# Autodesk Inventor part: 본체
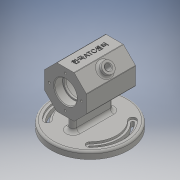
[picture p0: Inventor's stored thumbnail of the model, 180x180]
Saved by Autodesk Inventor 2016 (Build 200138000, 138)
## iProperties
Created: 2017-06
Part Number: 본체
Material: 일반
Document SubType Name: Modeling
Designer: USER
Density: 1 g/cm^3
Appearance: 기본값
Author: USER
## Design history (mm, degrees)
sketch "스케치1"
  geometry: L1 (0, 0)-(0, 30); L2 (0, 0)-(-12.426, 30); L3 (0, 0)-(12.426, 30); L4 (0, 0)-(12.426, -30); L5 (0, 0)-(-12.426, -30); L6 (0, 0)-(30, 12.426); L7 (0, 0)-(30, -12.426); L8 (0, 0)-(-30, 12.426); L9 (0, 0)-(-30, -12.426); L10 (0, 0)-(30, 0); L11 (0, 0)-(-30, 0); L12 (0, 0)-(0, -30); L13 (30, 12.426)-(30, -12.426); L14 (-12.426, -30)-(12.426, -30); L15 (-30, 12.426)-(-30, -12.426); L16 (-12.426, 30)-(12.426, 30); L17 (-12.426, 30)-(-30, 12.426); L18 (12.426, 30)-(30, 12.426); L19 (30, -12.426)-(12.426, -30); L20 (-12.426, -30)-(-30, -12.426); A1 r 30 centre (0, 0) between (0, 30) and (-30, 0); 7 further points
  constraints: 40 end point, 4 horizontal, 4 point on circle, 4 point on line, 4 vertical, 3 horizontal alignment, 2 vertical alignment, 1 centre point, 1 coincident, 1 perpendicular
  dimensions: "d0" = 60 diameter of A1; "d1" = 22.5 deg angle of L1 L2; "d2" = 22.5 deg angle of L1 L3; "d4" = 22.5 deg angle of L11 L8; "d5" = 22.5 deg angle of L11 L9; "d6" = 22.5 deg angle of L12 L5; "d7" = 22.5 deg angle of L4 L12; "d8" = 22.5 deg angle of L10 L7
extrude "돌출1" new body sketch "스케치1" distance "d9" = 70; taper "d10" = 0 deg
sketch "스케치2"
  geometry: L1 (0, 0)-(0, 70); L2 (-12.426, 0)-(-30, 0) reference; L3 (-16, 0)-(-16, 12); L4 (-16, 12)-(-14, 12); L5 (-14, 12)-(-14, 15); L6 (-14, 15)-(-25, 15); L7 (-25, 15)-(-25, 55); L8 (-25, 55)-(-14, 55); L9 (-14, 55)-(-14, 58); L10 (-14, 58)-(-16, 58); L11 (-16, 58)-(-16, 70); L12 (-12.426, 70)-(-30, 70) reference; L13 (-16, 70)-(0, 70); L14 (-16, 0)-(0, 0)
  constraints: 24 end point, 7 perpendicular, 3 point on line, 3 vertical, 1 horizontal, 1 parallel
  dimensions: "d11" = 32 diameter of L3 L1; "d12" = 32 diameter of L11 L1; "d13" = 28 diameter of L5 L1; "d14" = 50 diameter of L7 L1; "d15" = 12 distance of L3.start L3.end; "d16" = 12 distance of L10.end L11.end; "d17" = 40 distance of L6.end L7.end; "d18" = 3 distance of L8.end L9.end
revolve "회전1" sketch "스케치2" stored, may be unused: angle "d19" = 90 deg
sketch "스케치3" dims "d20" = 46
  geometry: 3 further points
  constraints: 2 coincident, 2 horizontal alignment, 2 other
hole "구멍1" sketch "스케치3" at (-23, 0) diameter "d21" = 3.242; stored, may be unused: countersink angle "d25" = 90 deg, drill point angle "d27" = 118 deg; dims "d22" = 8, "d23" = 4, "d24" = 2, "d26" = 10
node "작업 평면1"
chamfer "모따기1" distance "d31" = 1; stored, may be unused: second distance "d32" = 2, angle "d33" = 45 deg
fillet "모깎기1" dims "d34" = 3
fillet "모깎기2" dims "d35" = 0.3
node "작업 평면2"
sketch "스케치4"
  geometry: L1 (0, 30)-(70, 30) reference; C1 r 55 at (35, 0); 2 further points
  constraints: 1 centre point, 1 horizontal alignment, 1 midpoint, 1 vertical alignment
  dimensions: "d37" = 110 diameter of C1
extrude "돌출2" join sketch "스케치4" distance "d38" = 10; taper "d39" = 0 deg
sketch "스케치5"
  geometry: L1 (0, -24)-(0, 24); L2 (5, -24)-(5, 24); L3 (-5, 24)-(-5, -24); C1 r 55 at (0, 0) reference; A1 r 5 centre (0, -24) between (-5, -24) and (5, -24); A2 r 5 centre (0, 24) between (5, 24) and (-5, 24); 2 further points
  constraints: 8 end point, 4 point on circle, 4 tangent, 2 centre point, 1 coincident, 1 midpoint, 1 parallel, 1 vertical, 1 vertical alignment
  dimensions: "d40" = 5 radius of A1; "d41" = 48 distance of L1.end L1.start
extrude "돌출3" join sketch "스케치5" stored distance "d42" = 10; taper "d43" = 0 deg
fillet "모깎기3" dims "d44" = 5
sketch "스케치6"
  geometry: L1 (0, 0)-(30.406, 30.406); L2 (0, 0)-(72.385, 0); L3 (0, 0)-(-55, 0); L4 (0, 0)-(30.406, -30.406); L5 (0, 0)-(-30.406, -30.406); L6 (0, 0)-(-30.406, 30.406); A1 r 5 centre (30.406, -30.406) between (26.87, -26.87) and (33.941, -33.941); A2 r 5 centre (30.406, 30.406) between (33.941, 33.941) and (26.87, 26.87); A3 r 5 centre (-30.406, 30.406) between (-26.87, 26.87) and (-33.941, 33.941); A4 r 5 centre (-30.406, -30.406) between (-33.941, -33.941) and (-26.87, -26.87); A5 r 38 centre (0, 0) between (-26.87, 26.87) and (-26.87, -26.87); A6 r 38 centre (0, 0) between (26.87, -26.87) and (26.87, 26.87); A7 r 48 centre (0, 0) between (-33.941, 33.941) and (-33.941, -33.941); A8 r 48 centre (0, 0) between (33.941, -33.941) and (33.941, 33.941); 1 further point
  constraints: 16 point on circle, 12 end point, 8 centre point, 5 point on line, 3 coincident, 2 horizontal, 1 horizontal alignment, 1 other
  dimensions: "d49" = 45 deg angle of L2 L1; "d51" = 10 diameter of A1; "d52" = 10 diameter of A2; "d57" = 10 diameter of A3; "d58" = 10 diameter of A4; "d59" = 45 deg angle of L2 L4; "d60" = 45 deg angle of L3 L5; "d61" = 45 deg angle of L6 L3; "d62" = 38 radius of A6; "d63" = 48 radius of A8; "d64" = 38 radius of A5; "d65" = 48 radius of A7
extrude "돌출4" cut sketch "스케치6" distance "d66" = 3; taper "d67" = 0 deg
sketch "스케치7"
  geometry: L1 (0, 0)-(69.77, 0); L2 (0, 0)-(30.406, 30.406); L3 (0, 0)-(-74.571, 0); L4 (0, 0)-(30.406, -30.406); L5 (0, 0)-(-30.406, -30.406); L6 (0, 0)-(-30.406, 30.406); C1 r 55 at (0, 0) reference; A1 r 2 centre (30.406, 30.406) between (31.82, 31.82) and (28.991, 28.991); A2 r 2 centre (30.406, -30.406) between (28.991, -28.991) and (31.82, -31.82); A3 r 2 centre (-30.406, -30.406) between (-31.82, -31.82) and (-28.991, -28.991); A4 r 2 centre (-30.406, 30.406) between (-28.991, 28.991) and (-31.82, 31.82); A5 r 41 centre (0, 0) between (-28.991, 28.991) and (-28.991, -28.991); A6 r 41 centre (0, 0) between (28.991, -28.991) and (28.991, 28.991); A7 r 45 centre (0, 0) between (-31.82, 31.82) and (-31.82, -31.82); A8 r 45 centre (0, 0) between (31.82, -31.82) and (31.82, 31.82); 1 further point
  constraints: 16 point on circle, 12 end point, 8 centre point, 7 coincident, 2 horizontal, 1 horizontal alignment, 1 vertical alignment
  dimensions: "d70" = 45 deg angle of L1 L2; "d73" = 45 deg angle of L1 L4; "d74" = 45 deg angle of L3 L5; "d75" = 45 deg angle of L6 L3; "d76" = 4 diameter of A1; "d77" = 4 diameter of A2; "d78" = 4 diameter of A3; "d79" = 4 diameter of A4; "d82" = 41 radius of A6; "d83" = 45 radius of A8; "d84" = 41 radius of A5; "d85" = 45 radius of A7; "d86" = 30.40559 distance from line of L1 L2.end
extrude "돌출5" cut sketch "스케치7" distance "d87" = 20; taper "d88" = 0 deg
node "작업 평면3"
sketch "스케치8"
  geometry: L1 (0, 0)-(-26.163, -26.163); L2 (0, 0)-(-40.912, 0)
  constraints: 4 end point, 1 horizontal
  dimensions: "d89" = 45 deg angle of L2 L1; "d90" = 37 distance of L1.start L1.end
node "작업 평면4"
sketch "스케치9"
  geometry: L1 (-35, 12.426)-(-35, -12.426) reference; L2 (-35, -12.426)-(35, -12.426) reference; L3 (35, 12.426)-(35, -12.426) reference; L4 (-35, 12.426)-(35, 12.426) reference; C1 r 8 at (0, 0); 4 further points
  constraints: 2 midpoint, 1 centre point, 1 coincident, 1 horizontal alignment, 1 vertical alignment
  dimensions: "d91" = 16 diameter of C1
extrude "돌출6" join sketch "스케치9" stored distance "d92" = 20; taper "d93" = 0 deg
sketch "스케치11"
  geometry: C1 r 4 at (0, 0); C2 r 8 at (0, 0) reference; 1 further point
  constraints: 2 coincident, 1 centre point
  dimensions: "d94" = 8 diameter of C1
extrude "돌출7" cut sketch "스케치11" distance "d95" = 30; taper "d96" = 0 deg
fillet "모깎기4" dims "d97" = 3
chamfer "모따기2" distance "d98" = 1; stored, may be unused: second distance "d99" = 2, angle "d100" = 45 deg
fillet "모깎기5" dims "d101" = 3
fillet "모깎기6" dims "d102" = 1
sketch "스케치12"
  geometry: L1 (-17.695, 0)-(-0.707, 0) reference; L2 (-17.988, 70)-(-17.988, 0) reference; 2 further points
  constraints: 1 other
  dimensions: "d103" = 35 distance from line of L1 point (12.012, 35); "d108" = 30 distance from line of point (12.012, 35) L2
feature "엠보싱1" sketch "스케치12" dims "d0" = 60, "d1" = 22.5 deg, "d2" = 22.5 deg, "d4" = 22.5 deg, "d5" = 22.5 deg, "d6" = 22.5 deg, "d7" = 22.5 deg, "d8" = 22.5 deg, "d105" = 0.5, "d106" = 0
node "작업 평면5"
node "솔리드1"
pattern_circular "원형 패턴1" dims angle "d29" = 360 deg
mirror "대칭1"
node "투영된 루프1"
node "투영된 루프3"
node "투영된 루프4"
other parameters: "d36" = -62, "d47" = 86, "d48" = 45 deg, "d53" = 96, "d54" = 76, "d55" = 45 deg, "d56" = 45 deg, "d68" = 86, "d69" = 45 deg, "d71" = 45 deg, "d72" = 45 deg, "d81" = 82, "d107" = 2
